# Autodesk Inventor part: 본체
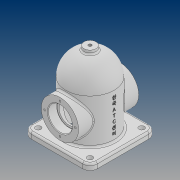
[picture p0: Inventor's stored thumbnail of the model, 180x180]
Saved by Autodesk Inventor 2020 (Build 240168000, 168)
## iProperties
Created: 2021-08
Part Number: 본체
Material: 일반
Document SubType Name: Modeling
Designer: PC312-
Density: 1 g/cm^3
Appearance: 기본값
Mass: 320.706 g
Surface Area: 800.755 cm^2
Volume: 320.706 cm^3
Author: PC312-
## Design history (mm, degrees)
sketch "스케치1"
  geometry: L1 (0, 0)-(124, 0); L2 (0, 0)-(0, -40); L3 (0, -40)-(84, -40); A1 r 40 centre (84, 0) between (84, -40) and (44, 0); 1 further point
  constraints: 6 end point, 2 horizontal, 2 point on circle, 1 centre point, 1 horizontal alignment, 1 point on line, 1 tangent, 1 vertical
  dimensions: "d1" = 124 distance of L1.start L1.end; "d4" = 80 diameter of A1; "d5" = 84 distance from line of L2 A1.centre
revolve "회전1" sketch "스케치1" stored, may be unused: angle "d6" = 90 deg
feature "쉘1" dims "d7" = 8
sketch "스케치2"
  geometry: L1 (-55, 55)-(55, 55); L2 (55, 55)-(55, -55); L3 (55, -55)-(-55, -55); L4 (-55, -55)-(-55, 55); L5 (-55, 55)-(55, -55); L6 (55, 55)-(-55, -55); C1 r 40 at (0, 0) reference; 1 further point
  constraints: 12 end point, 2 midpoint, 2 parallel, 1 horizontal, 1 perpendicular
  dimensions: "d8" = 110 distance of L2.end L3.end; "d9" = 110 distance of L1.end L2.end
extrude "돌출1" join sketch "스케치2" distance "d10" = 10; taper "d11" = 0 deg
node "작업 평면1"
sketch "스케치3"
  geometry: L1 (55, 0)-(-55, 0) reference; C1 r 31 at (0, 48); 2 further points
  constraints: 1 centre point, 1 midpoint, 1 vertical alignment
  dimensions: "d13" = 62 diameter of C1; "d14" = 48 distance from line of L1 C1.centre
extrude "돌출2" join sketch "스케치3" stored distance "d15" = 10; taper "d16" = 0 deg
sketch "스케치4"
  geometry: C1 r 31 at (0, 0) reference; C2 r 20 at (0, 0); 1 further point
  constraints: 1 centre point, 1 coincident
  dimensions: "d17" = 40 diameter of C2
extrude "돌출3" cut sketch "스케치4" distance "d18" = 15; taper "d19" = 0 deg
sketch "스케치5"
  geometry: C1 r 20 at (0, 0) reference; C2 r 16.5 at (0, 0); 1 further point
  constraints: 1 centre point, 1 coincident
  dimensions: "d20" = 33 diameter of C2
extrude "돌출4" cut sketch "스케치5" distance "d21" = 15; taper "d22" = 0 deg
node "작업 평면2"
sketch "스케치6"
  geometry: C1 r 10 at (0, 0); 1 further point
  constraints: 1 centre point, 1 coincident
  dimensions: "d24" = 20 diameter of C1
extrude "돌출5" join sketch "스케치6" stored distance "d25" = 15; taper "d26" = 0 deg
sketch "스케치7"
  geometry: C1 r 10 at (0, 0) reference; 2 further points
  constraints: 1 coincident
hole "구멍1" sketch "스케치7" at (0, 0) diameter "d27" = 5.1881; stored, may be unused: countersink angle "d31" = 90 deg, drill point angle "d33" = 0 deg; dims "d28" = 12, "d29" = 4, "d30" = 2, "d32" = 16
sketch "스케치8"
  geometry: C1 r 31 at (0, 0) reference; 2 further points
  constraints: 1 vertical alignment
  dimensions: "d34" = 25.5 distance of C1.centre point (0, 25.5)
hole "구멍2" sketch "스케치8" at (0, 25.5) diameter "d35" = 3.242; stored, may be unused: countersink angle "d39" = 90 deg, drill point angle "d41" = 118 deg; dims "d36" = 8, "d37" = 4, "d38" = 2, "d40" = 10
fillet "모깎기1" dims "d45" = 12
sketch "스케치9"
  geometry: C1 r 4.5 at (-43, 43); C2 r 4.5 at (-43, -43); C3 r 4.5 at (43, -43); C4 r 4.5 at (43, 43); A1 r 12 centre (-43, 43) between (-43, 55) and (-55, 43) reference; A2 r 12 centre (43, 43) between (55, 43) and (43, 55) reference; A3 r 12 centre (43, -43) between (43, -55) and (55, -43) reference; A4 r 12 centre (-43, -43) between (-55, -43) and (-43, -55) reference; 1 further point
  constraints: 4 centre point, 4 coincident
  dimensions: "d46" = 9 diameter of C1; "d47" = 9 diameter of C2; "d48" = 9 diameter of C3; "d49" = 9 diameter of C4
extrude "돌출6" cut sketch "스케치9" extent not by distance; stored distance "d50" = 0; taper "d51" = 0 deg
node "작업 평면3"
sketch "스케치10"
  geometry: L1 (0, -43)-(0, 43) reference; 3 further points
  constraints: 1 horizontal alignment, 1 midpoint, 1 other
  dimensions: "d53" = 48 distance from line of L1 point (48, 0)
feature "엠보싱1" sketch "스케치10" dims "d1" = 124, "d4" = 80, "d5" = 84, "d54" = 0.5, "d55" = 0
chamfer "모따기1" distance "d56" = 1; stored, may be unused: second distance "d57" = 2, angle "d58" = 45 deg
fillet "모깎기2" dims "d59" = 0.3
fillet "모깎기3" dims "d60" = 3
node "솔리드1"
mirror "미러1"
pattern_circular "원형 패턴1" dims angle "d43" = 360 deg
mirror "미러2"
feature "A9D066F2-1C7D-4E18-AEED-F7BC21143FA4" dims "d27" = 5.1881, "d28" = 12, "d29" = 4, "d30" = 2, "d31" = 90 deg, "d32" = 16, "d33" = 0
other parameters: "d23" = 129, "d52" = 77
